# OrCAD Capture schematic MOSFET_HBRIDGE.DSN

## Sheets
1 PAGE1: size A
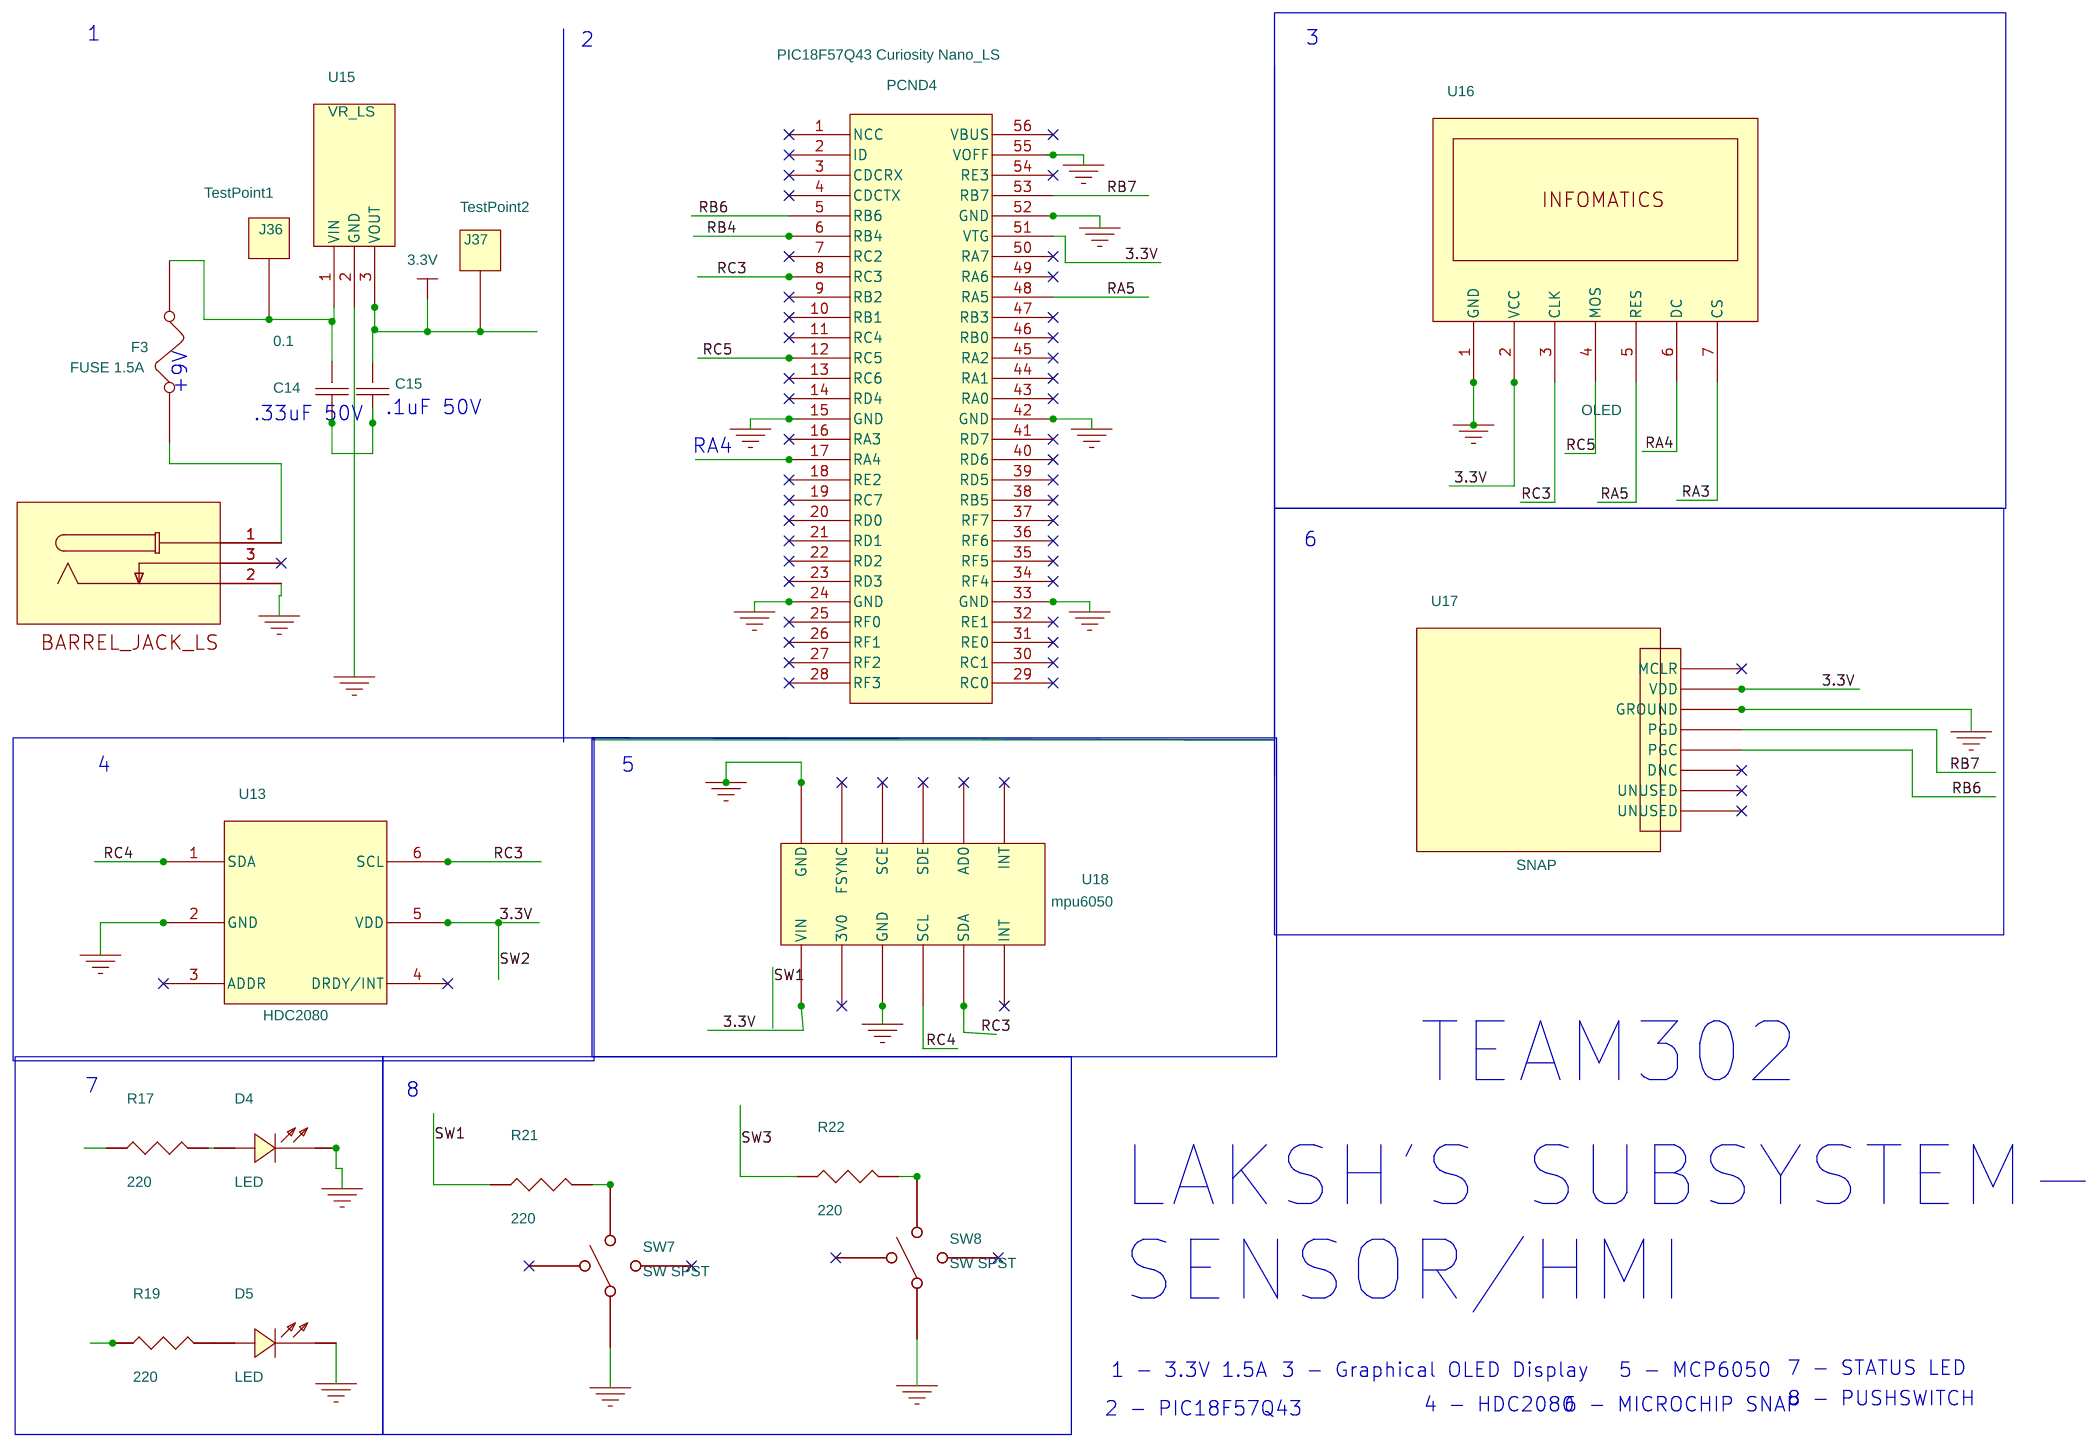
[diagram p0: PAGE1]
2 PAGE5: size A
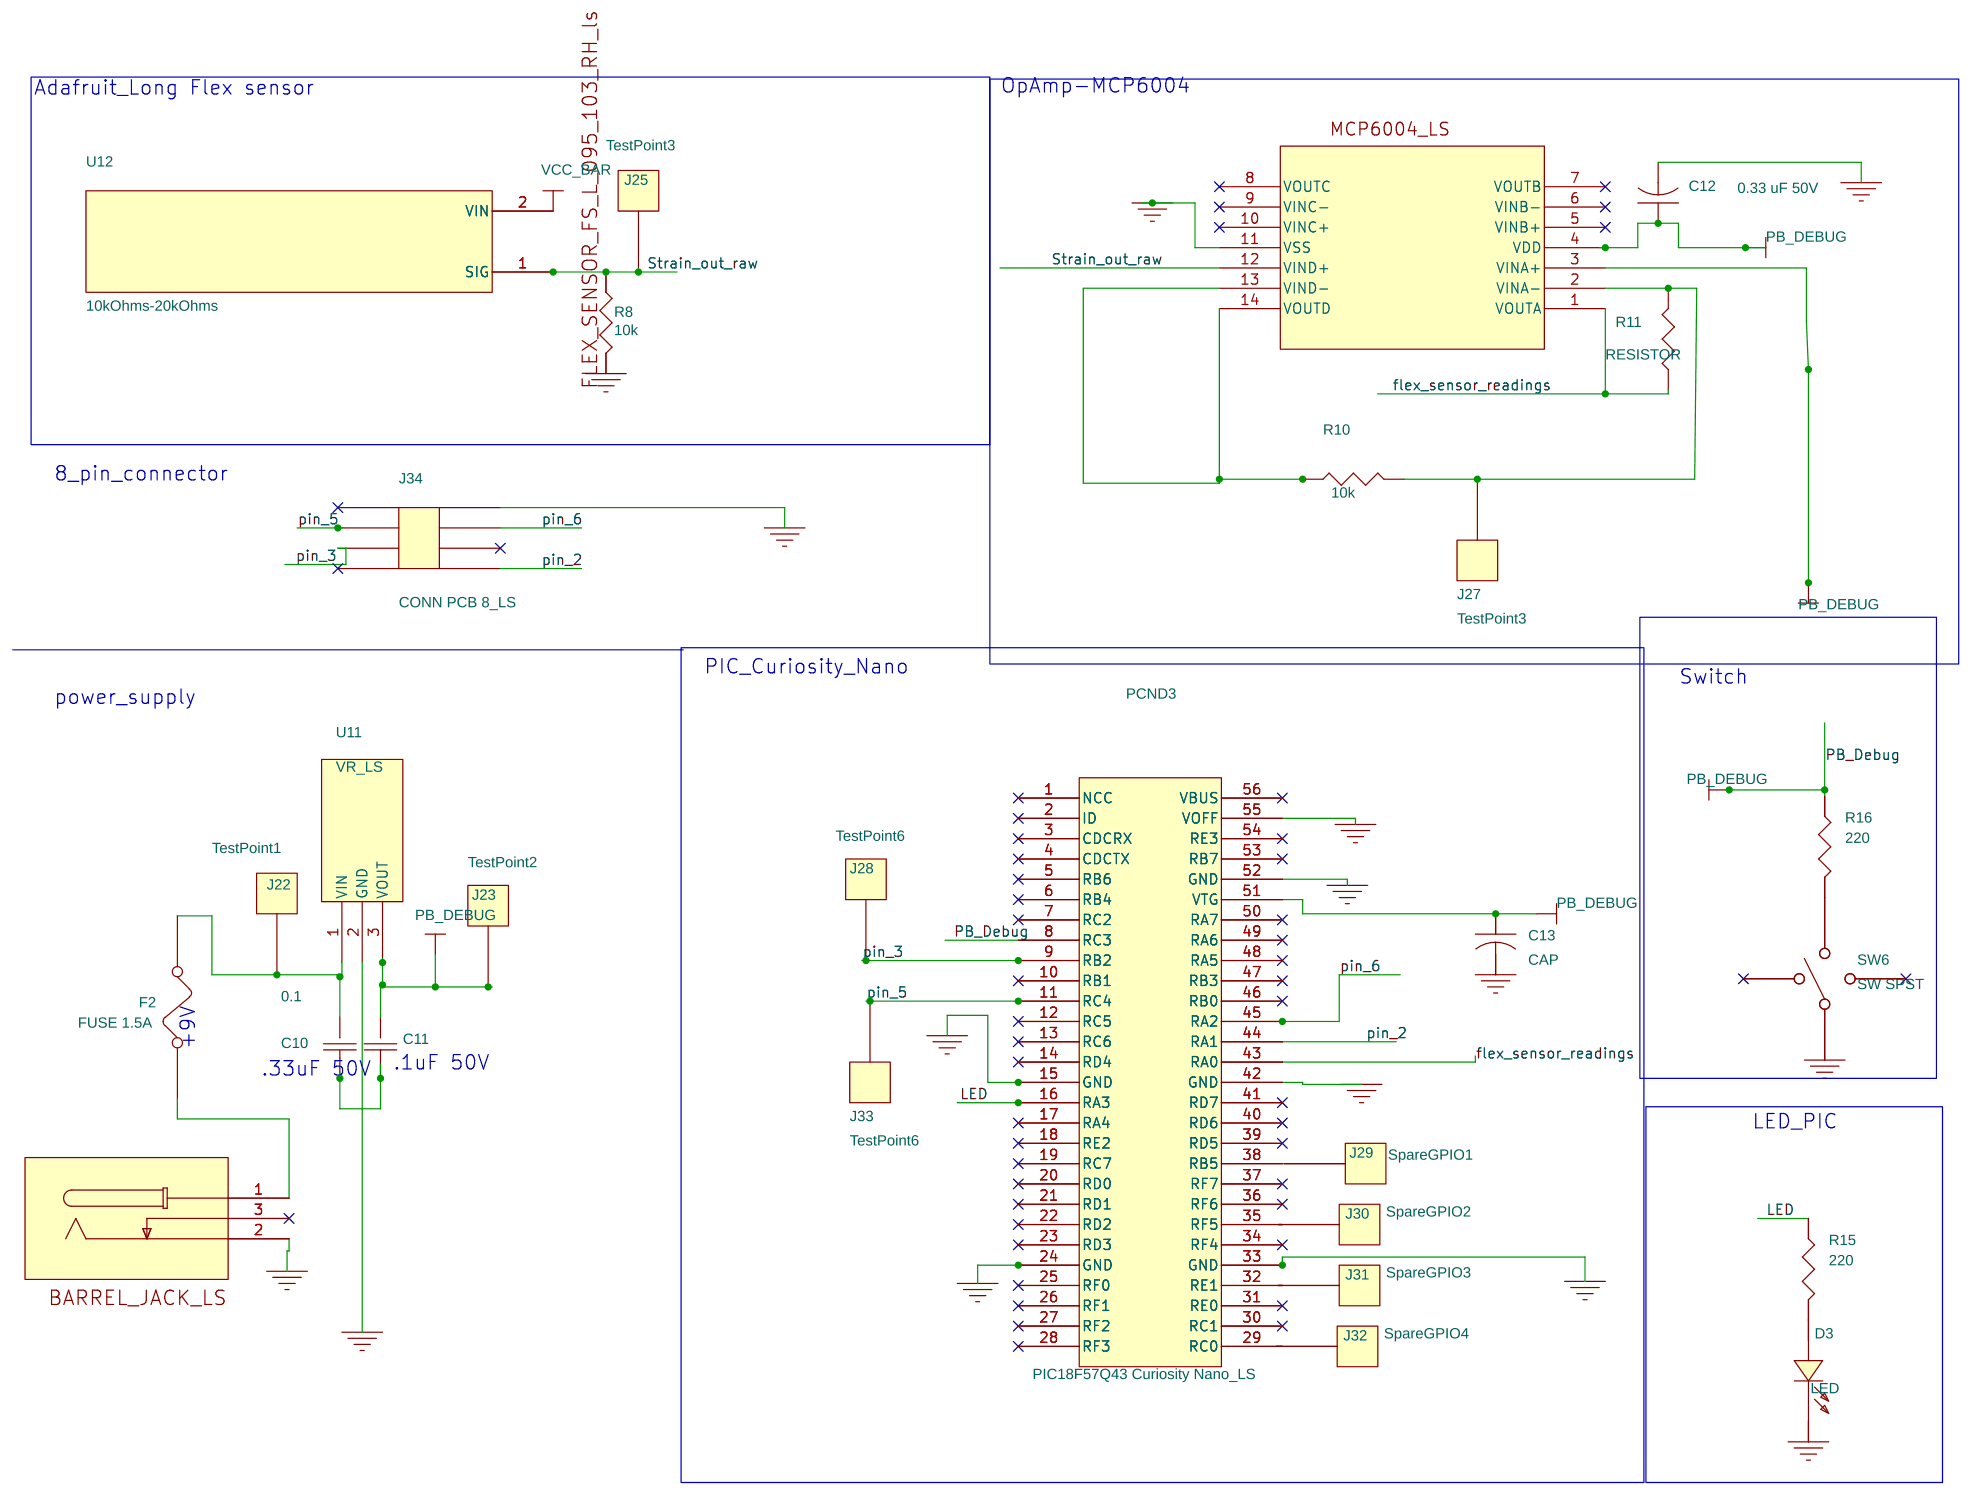
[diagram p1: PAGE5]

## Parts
sheet PAGE1
C14  0.1  [resistor_th]
C15  CAP  [resistor_th]
D4  LED  [hdr_1x02_2]
D5  LED  [hdr_1x02_2]
F3  FUSE 1.5A  [FUSE_01550900M_LTF]
J36  TestPoint1  [connectoronepin]
J37  TestPoint2  [connectoronepin]
J38  B_JACK  [NEB21R_LMB]
PCND4  PIC18F57Q43 Curiosity Nano_LS  [56pins-pic]
R17  220  [resistor_th]
R19  220  [resistor_th]
R21  220  [resistor_th]
R22  220  [resistor_th]
SW7  SW SPST  [pusbutton]
SW8  SW SPST  [pusbutton]
U13  HDC2080
U15  VR_LS  [to220-3_ons]
U16  OLED
U17  SNAP
U18  mpu6050
sheet PAGE5
C10  0.1  [resistor_th]
C11  CAP  [resistor_th]
C12  0.33 uF 50V  [resistor_th]
C13  CAP  [resistor_th]
D3  LED  [hdr_1x02_2]
F2  FUSE 1.5A  [FUSE_01550900M_LTF]
J22  TestPoint1  [connectoronepin]
J23  TestPoint2  [connectoronepin]
J25  TestPoint3  [connectoronepin]
J27  TestPoint3  [connectoronepin]
J28  TestPoint6  [connectoronepin]
J29  SpareGPIO1  [connectoronepin]
J30  SpareGPIO2  [connectoronepin]
J31  SpareGPIO3  [connectoronepin]
J32  SpareGPIO4  [connectoronepin]
J33  TestPoint6  [connectoronepin]
J34  CONN PCB 8_LS  [CONN_61200821621_WRE]
J35  B_JACK  [NEB21R_LMB]
PCND3  PIC18F57Q43 Curiosity Nano_LS  [56pins-pic]
R8  10k  [resistor_th]
R10  10k  [resistor_th]
R11  RESISTOR  [resistor_th]
R15  220  [resistor_th]
R16  220  [resistor_th]
SW6  SW SPST  [pusbutton]
U11  VR_LS  [to220-3_ons]
U12  10kOhms-20kOhms  [hdr_1x02_2]
U14  MCP6004  [SOIC14-N_MC_MCH]

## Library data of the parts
C10 C11 C14 C15 = MKP1839410084HQ
D3-D5 = LED
F2 F3 = FUSE_SM
J22 J23 J25 J27-J33 J36 J37 = CON1
J35 J38 = B_JACK
PCND3 PCND4 = PIC18F57Q10_18
R8 R10 R11 R15-R17 R19 R21 R22 = RESISTOR
SW6-SW8 = SW_SPST_1
U13 = TH_SENSOR
U11 U15 = VR_LS_11
U16 = OLED
U17 = Snap
U18 = imu
C12 C13 = CAP
J34 = CONN_PCB_8_2
U12 = FLEX_SENSOR_FS_L_095_103_RH_0
U14 = MCP6004_0

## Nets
3.3V: C15.2 J37.1 PCND4.51(VTG) U13.5(VDD) U15.3(VOUT) U16.2(VCC) U17.VDD U18.VIN
5V: C11.2 C12.1 C13.1 J23.1 PCND3.8(RC3) PCND3.51(VTG) R16.1 U11.3(VOUT) U12.2(VIN) U14.3(VINA+) U14.4(VDD)
GND: C12.2 C13.2 D3.1(CATHODE) D4.1(CATHODE) D5.1(CATHODE) J34.8 J35.2 J38.2 PCND3.15(GND) PCND3.24(GND) PCND3.33(GND) PCND3.42(GND) PCND3.52(GND) PCND3.55(VOFF) PCND4.15(GND) PCND4.24(GND) PCND4.33(GND) PCND4.42(GND) PCND4.52(GND) PCND4.55(VOFF) R8.2 SW6.1 SW7.1 SW8.1 U11.2(GND) U14.11(VSS) U15.2(GND) U16.1(GND) U17.GROUND U18.GND
0: U13.2(GND)
flex_sensor_readings: PCND3.43(RA0) R11.1 U14.1(VOUTA)
LED: PCND3.16(RA3) R15.1
pin_2: J34.2 PCND3.44(RA1)
pin_3: J28.1 J34.3 PCND3.9(RB2)
pin_5: J33.1 J34.5 PCND3.11(RC4)
pin_6: J34.6 PCND3.45(RA2)
RA3: U16.7(CS)
RA4: U16.6(DC)
RA5: PCND4.48(RA5) U16.5(RES)
RB4: PCND4.6(RB4)
RB6: PCND4.5(RB6) U17.PGC
RB7: PCND4.53(RB7) U17.PGD
RC3: PCND4.8(RC3) U13.6(SCL) U16.3(CLK) U18.SDA
RC4: U13.1(SDA) U18.SCL
RC5: PCND4.12(RC5) U16.4(MOS)
Strain_out_raw: J25.1 R8.1 U12.1(SIG) U14.12(VIND+)
SW1: R21.1
SW3: R22.1
N106824: C10.2 F2.2 J22.1 U11.1(VIN)
N106956: C10.1 C11.1
N108303: R10.1 U14.13(VIND-) U14.14(VOUTD)
N108415: J27.1 R10.2 R11.2 U14.2(VINA-)
N113032: J30.1 PCND3.35(RF5)
N114337: J31.1 PCND3.32(RE1)
N114341: J32.1 PCND3.29(RC0)
N122941: F2.1 J35.1
N130921: R16.2 SW6.3
N130968: D3.2(ANODE) R15.2
N131001: J29.1 PCND3.38(RB5)
N133960: C14.2 F3.2 J36.1 U15.1(VIN)
N134108: C14.1 C15.1
N134156: F3.1 J38.1
N134858: D4.2(ANODE) R17.2
N134984: D5.2(ANODE) R19.2
N135361: R21.2 SW7.3
N137183: R22.2 SW8.3

Not connected (* = marked no-connect by the designer): J34 1* 4* 7*; J35 3*; J38 3*; PCND3 1(NCC)* 2(ID)* 3(CDCRX)* 4(CDCTX)* 5(RB6)* 6(RB4)* 7(RC2)* 10(RB1)* 12(RC5)* 13(RC6)* 14(RD4)* 17(RA4)* 18(RE2)* 19(RC7)* 20(RD0)* 21(RD1)* 22(RD2)* 23(RD3)* 25(RF0)* 26(RF1)* 27(RF2)* 28(RF3)* 30(RC1)* 31(RE0)* 34(RF4)* 36(RF6)* 37(RF7)* 39(RD5)* 40(RD6)* 41(RD7)* 46(RB0)* 47(RB3)* 48(RA5)* 49(RA6)* 50(RA7)* 53(RB7)* 54(RE3)* 56(VBUS)*; PCND4 1(NCC)* 2(ID)* 3(CDCRX)* 4(CDCTX)* 7(RC2)* 9(RB2)* 10(RB1)* 11(RC4)* 13(RC6)* 14(RD4)* 16(RA3)* 17(RA4) 18(RE2)* 19(RC7)* 20(RD0)* 21(RD1)* 22(RD2)* 23(RD3)* 25(RF0)* 26(RF1)* 27(RF2)* 28(RF3)* 29(RC0)* 30(RC1)* 31(RE0)* 32(RE1)* 34(RF4)* 35(RF5)* 36(RF6)* 37(RF7)* 38(RB5)* 39(RD5)* 40(RD6)* 41(RD7)* 43(RA0)* 44(RA1)* 45(RA2)* 46(RB0)* 47(RB3)* 49(RA6)* 50(RA7)* 54(RE3)* 56(VBUS)*; R17 1; R19 1; SW6 2* 4*; SW7 2* 4*; SW8 2* 4*; U13 3(ADDR)* 4(DRDY/INT)*; U14 5(VINB+)* 6(VINB-)* 7(VOUTB)* 8(VOUTC)* 9(VINC-)* 10(VINC+)*; U17 DNC* MCLR* UNUSED*; U18 3V0* AD0* FSYNC* INT* SCE* SDE*

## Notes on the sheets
sheet 1
- 1
- 2
- 3
- +9V
- .1uF 50V
- .33uF 50V
- RA4
- 6
- 4
- 5
- TEAM302
- 7
- 8
- LAKSH'S SUBSYSTEM-
  SENSOR/HMI
- 1 - 3.3V 1.5A
- 3 - Graphical OLED Display
- 5 - MCP6050
- 7 - STATUS LED
- 2 - PIC18F57Q43
- 4 - HDC2080
- 6 - MICROCHIP SNAP
- 8 - PUSHSWITCH
sheet 2
- Adafruit_Long Flex sensor
- OpAmp-MCP6004
- 8_pin_connector
- PIC_Curiosity_Nano
- Switch
- power_supply
- +9V
- .33uF 50V
- .1uF 50V
- LED_PIC
